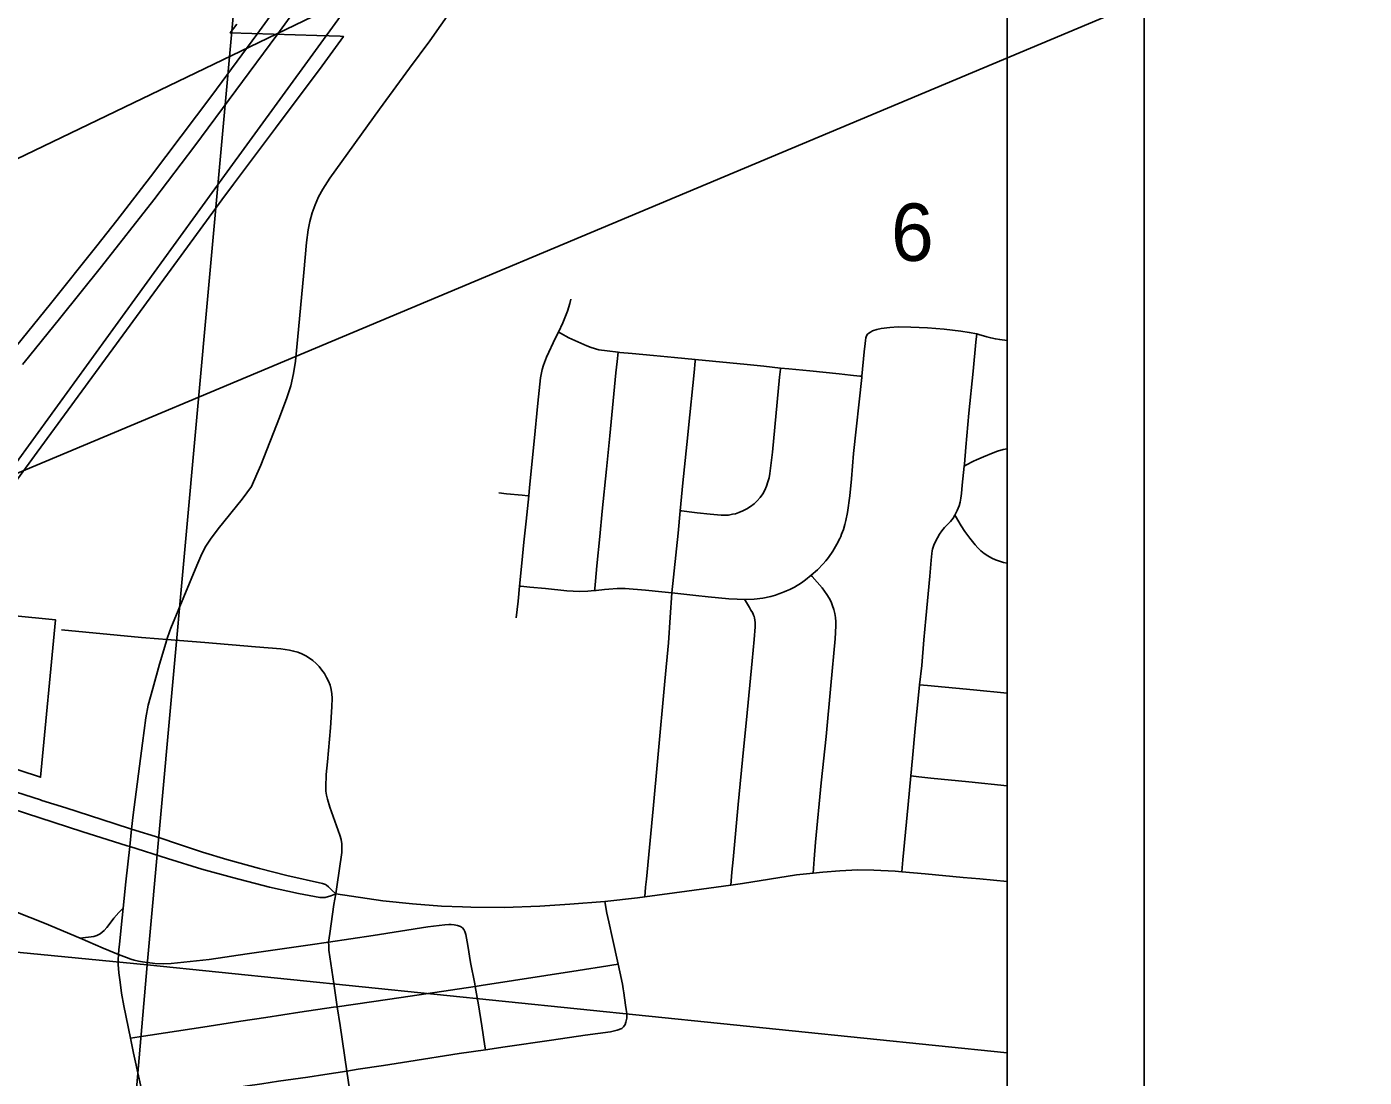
# Model space of a CAD drawing. Extents: x 0 to 34, y 0 to 22.
# Drawn here: x 8.184 to 9.161, y 18.991 to 19.757 of the extents above; entities that cross this region are included whole.
import ezdxf

# ---------------------------------------------------------------- set-up
doc = ezdxf.new("R2010")
doc.units = 0
for name, color, linetype in [('Default', 7, 'Continuous'), ('GM_X_City_Street', 7, 'Continuous'), ('GM_X_County_Road', 7, 'Continuous'), ('GM_X_Rail_Line', 7, 'Continuous'), ('GM_X_Section', 7, 'Continuous'), ('GM_X_Section_Text', 7, 'Continuous'), ('GM_X_State_Route', 7, 'Continuous'), ('GM_X_Township_Road', 7, 'Continuous'), ('GM_X_US_Route', 7, 'Continuous'), ('SC_Shading1', 7, 'Continuous'), ('SH_Data', 7, 'Continuous'), ('SH_Text', 7, 'Continuous')]:
    doc.layers.add(name, color=color, linetype=linetype)

msp = doc.modelspace()

# ---------------------------------------------------------------- linework, layer by layer
at = {"layer": 'Default'}
for points in [[(8.9, 19.00882), (8.9, 20.02755), (8.36301, 20.07599), (8.27199, 19.07297)], [(8.9, 18.00303), (8.9, 19.00882), (8.27199, 19.07297), (8.18593, 18.07293)]]:
    msp.add_lwpolyline(points, close=True, dxfattribs=at)
at = {"layer": 'GM_X_City_Street'}
for points in [[(8.9, 14.09996), (8.9, 20.03076), (8.89121, 20.03126), (8.71075, 20.04151), (8.58587, 20.05322), (8.57205, 20.0545), (8.0393, 20.10354)], [(8.54139, 19.32601), (8.54279, 19.33829), (8.54387, 19.34932), (8.54551, 19.36594), (8.54698, 19.38132), (8.54866, 19.39664), (8.55059, 19.41517), (8.55122, 19.42117), (8.55464, 19.45502), (8.55716, 19.48275), (8.5593, 19.50122), (8.56043, 19.50739), (8.56132, 19.51041), (8.5636, 19.51626), (8.57026, 19.53027), (8.57229, 19.53455), (8.57551, 19.54135), (8.5789, 19.54971), (8.58071, 19.5555), (8.58137, 19.55847)], [(8.79891, 19.53383), (8.8, 19.53453), (8.80162, 19.53538), (8.80463, 19.53638), (8.80798, 19.53717), (8.81415, 19.53802), (8.82035, 19.53832), (8.82965, 19.5382), (8.84178, 19.53777), (8.85398, 19.53672), (8.86615, 19.53534), (8.87222, 19.53436), (8.87762, 19.53323)], [(8.54387, 19.34932), (8.54473, 19.34924), (8.55142, 19.34859), (8.56297, 19.34743), (8.57836, 19.34578), (8.58757, 19.34537), (8.59371, 19.34558), (8.59861, 19.346), (8.59986, 19.34611), (8.606, 19.34674), (8.60905, 19.34704), (8.61509, 19.34744), (8.62099, 19.34756), (8.62695, 19.34711), (8.62991, 19.34682), (8.63578, 19.34623), (8.6479, 19.34507), (8.65505, 19.34426), (8.67255, 19.3425), (8.68151, 19.34137), (8.69668, 19.34007), (8.70281, 19.33961), (8.70815, 19.33953), (8.71512, 19.33962), (8.72143, 19.34041), (8.72725, 19.3416), (8.7308, 19.34268), (8.73317, 19.34357), (8.7358, 19.34455), (8.737, 19.345), (8.73879, 19.34574), (8.74115, 19.34684), (8.74461, 19.34859), (8.74964, 19.35156), (8.7527, 19.35383), (8.75684, 19.35713), (8.76148, 19.36103), (8.76566, 19.36546), (8.76761, 19.36781), (8.76942, 19.37017), (8.77253, 19.37469), (8.77559, 19.37992), (8.77769, 19.38389), (8.77835, 19.38534), (8.77903, 19.38716), (8.78035, 19.3906), (8.78127, 19.39415), (8.78218, 19.39705), (8.78338, 19.403), (8.78499, 19.41518), (8.78615, 19.42756), (8.78782, 19.44591), (8.79368, 19.50153), (8.79378, 19.50236), (8.79549, 19.52013), (8.79618, 19.52623), (8.7964, 19.52851), (8.79675, 19.53027), (8.79729, 19.5319), (8.79798, 19.53298), (8.79891, 19.53383)], [(8.57229, 19.53455), (8.57377, 19.53373), (8.57998, 19.53028), (8.59297, 19.52448), (8.59631, 19.52322), (8.60172, 19.52172), (8.60788, 19.52083), (8.61579, 19.51988), (8.61705, 19.51973), (8.62616, 19.51889), (8.64163, 19.51745), (8.65707, 19.51597), (8.67215, 19.51459), (8.70997, 19.51088), (8.72225, 19.5096), (8.73439, 19.50835), (8.74048, 19.50772), (8.75573, 19.50622), (8.77734, 19.504), (8.78562, 19.50318), (8.79241, 19.5025), (8.79378, 19.50236)], [(8.82292, 19.1408), (8.82376, 19.14968), (8.82754, 19.18986), (8.82957, 19.21075), (8.83083, 19.22385), (8.83274, 19.24542), (8.83599, 19.27719), (8.83747, 19.29139), (8.83915, 19.31003), (8.84053, 19.32552), (8.84349, 19.35639), (8.84437, 19.36813), (8.84487, 19.37316), (8.84518, 19.37493), (8.84546, 19.37612), (8.84567, 19.3769), (8.84643, 19.37905), (8.84761, 19.38184), (8.84897, 19.38455), (8.85051, 19.38715), (8.85227, 19.38959), (8.85423, 19.39194), (8.85844, 19.39646), (8.86043, 19.39891), (8.86177, 19.40112), (8.86344, 19.40442), (8.86479, 19.40788), (8.86554, 19.41042), (8.86605, 19.41337), (8.86643, 19.41684), (8.86707, 19.42287), (8.86856, 19.43677), (8.86873, 19.43829), (8.86978, 19.45068), (8.87197, 19.47537), (8.8751, 19.50615), (8.87704, 19.52719), (8.87762, 19.53323)], [(8.59861, 19.346), (8.59877, 19.34757), (8.59928, 19.3529), (8.60034, 19.36405), (8.60253, 19.38545), (8.60423, 19.40385), (8.6073, 19.43452), (8.60993, 19.45894), (8.61432, 19.50483), (8.61513, 19.5131), (8.61579, 19.51988)], [(8.63531, 19.12253), (8.63596, 19.12972), (8.63649, 19.13553), (8.64139, 19.1868), (8.64493, 19.22401), (8.64995, 19.27986), (8.65255, 19.30777), (8.65398, 19.32636), (8.65505, 19.34426), (8.65973, 19.38786), (8.66123, 19.40419), (8.66171, 19.40937), (8.66319, 19.42466), (8.66595, 19.45267), (8.66812, 19.47408), (8.67048, 19.49568), (8.67132, 19.5051), (8.67213, 19.51327), (8.67215, 19.51459)], [(8.66123, 19.40419), (8.66239, 19.40406), (8.66763, 19.40347), (8.67354, 19.40278), (8.683, 19.40179), (8.6911, 19.401), (8.69326, 19.4009), (8.69504, 19.401), (8.69652, 19.4011), (8.69927, 19.40164), (8.70145, 19.40209), (8.70398, 19.40295), (8.70697, 19.40411), (8.70984, 19.40557), (8.71255, 19.40726), (8.71512, 19.4092), (8.71748, 19.41138), (8.71959, 19.41383), (8.72141, 19.41648), (8.72296, 19.41929), (8.72424, 19.42223), (8.72526, 19.42526), (8.72605, 19.42835), (8.7266, 19.43149), (8.72854, 19.447), (8.73376, 19.50161), (8.7343, 19.50743), (8.73439, 19.50835)], [(8.86856, 19.43677), (8.86975, 19.4374), (8.87526, 19.44032), (8.87759, 19.44144), (8.88264, 19.44357), (8.88965, 19.44658), (8.89286, 19.4477), (8.89695, 19.44887), (8.89995, 19.44949), (8.9, 19.4495)], [(8.52872, 19.41719), (8.53444, 19.41665), (8.54578, 19.41559), (8.54984, 19.41523), (8.55059, 19.41517)], [(8.86177, 19.40112), (8.8622, 19.40037), (8.86624, 19.39325), (8.86902, 19.38908), (8.87252, 19.38424), (8.87644, 19.3794), (8.87852, 19.3771), (8.88069, 19.375), (8.88312, 19.37309), (8.88589, 19.37125), (8.88865, 19.36967), (8.89126, 19.36852), (8.89427, 19.36735), (8.89723, 19.3664), (8.9, 19.36593)], [(8.75824, 19.13979), (8.75904, 19.15002), (8.76001, 19.16246), (8.76414, 19.20572), (8.76765, 19.23964), (8.77108, 19.27684), (8.77433, 19.31091), (8.77481, 19.32018), (8.77479, 19.32325), (8.77459, 19.32626), (8.77413, 19.32921), (8.77343, 19.33211), (8.77249, 19.33497), (8.77131, 19.33775), (8.76992, 19.34045), (8.76835, 19.34308), (8.7648, 19.34805), (8.76125, 19.35216), (8.75758, 19.35629), (8.75684, 19.35713)], [(8.69807, 19.13118), (8.69896, 19.14062), (8.69983, 19.14988), (8.70349, 19.19001), (8.70741, 19.2301), (8.70952, 19.25167), (8.71366, 19.29483), (8.71515, 19.31023), (8.71586, 19.31948), (8.71588, 19.32273), (8.71566, 19.32451), (8.71537, 19.32599), (8.71507, 19.32698), (8.71478, 19.32796), (8.71438, 19.32875), (8.71389, 19.32993), (8.71279, 19.33181), (8.71168, 19.33364), (8.70878, 19.33848), (8.70815, 19.33953)], [(8.40974, 19.12474), (8.41049, 19.12989), (8.41416, 19.15496), (8.41428, 19.15812), (8.41413, 19.16129), (8.41363, 19.16444), (8.41281, 19.16751), (8.40541, 19.18789), (8.40362, 19.19374), (8.40298, 19.19668), (8.4026, 19.19966), (8.40248, 19.20268), (8.4028, 19.21189), (8.40365, 19.2211), (8.40581, 19.24576), (8.40695, 19.26124), (8.40705, 19.2675), (8.40684, 19.27066), (8.40636, 19.2738), (8.40554, 19.27688), (8.40443, 19.27985), (8.40304, 19.2827), (8.40144, 19.28543), (8.39965, 19.28805), (8.39767, 19.29053), (8.39548, 19.29282), (8.3931, 19.29491), (8.39053, 19.29678), (8.3878, 19.29841), (8.38495, 19.2998), (8.382, 19.30096), (8.37898, 19.30184), (8.37591, 19.30252), (8.36971, 19.30338), (8.35119, 19.30504), (8.3142, 19.30823), (8.28653, 19.31033), (8.28026, 19.3108), (8.26795, 19.31187), (8.20947, 19.31744)], [(8.83599, 19.27719), (8.84181, 19.27665), (8.87519, 19.27364), (8.9, 19.27125)], [(8.82957, 19.21075), (8.83536, 19.21019), (8.84413, 19.20924), (8.87193, 19.20636), (8.9, 19.20357)], [(8.4224, 18.96438), (8.41777, 18.99547), (8.41298, 19.02868), (8.41087, 19.04237), (8.40825, 19.05931), (8.4048, 19.08375), (8.40464, 19.08678), (8.40452, 19.08955), (8.40532, 19.09591), (8.40828, 19.11695), (8.40974, 19.12474)], [(8.61866, 19.02659), (8.61975, 19.02767), (8.62103, 19.02945), (8.62162, 19.03103), (8.62231, 19.03409), (8.62216, 19.03736), (8.62182, 19.04038), (8.62133, 19.04366), (8.61993, 19.05262), (8.61945, 19.05549), (8.61895, 19.05881), (8.61714, 19.06793), (8.61593, 19.07336), (8.61175, 19.09227), (8.60909, 19.10432), (8.60775, 19.11062), (8.60613, 19.11909)], [(8.25123, 19.08047), (8.25688, 19.0783), (8.26011, 19.07722), (8.26247, 19.07646), (8.26579, 19.07576), (8.26859, 19.07522), (8.27767, 19.07397), (8.28364, 19.07359), (8.28963, 19.07393), (8.31738, 19.07686), (8.345, 19.08107), (8.39097, 19.08757), (8.40452, 19.08955), (8.43713, 19.09442), (8.47687, 19.10081), (8.48936, 19.10223), (8.49231, 19.10244), (8.49402, 19.10238), (8.49612, 19.10224), (8.49869, 19.10172), (8.50082, 19.10082)], [(8.51902, 19.01105), (8.51863, 19.01361), (8.51634, 19.02845), (8.51387, 19.04376), (8.51153, 19.05726), (8.51118, 19.05922), (8.50819, 19.07461), (8.50604, 19.08704), (8.50458, 19.09499), (8.5039, 19.09728), (8.50322, 19.09876), (8.50217, 19.10001), (8.50082, 19.10082)], [(8.25986, 19.01953), (8.26613, 19.02046), (8.31277, 19.02738), (8.34045, 19.03177), (8.3587, 19.03452), (8.38354, 19.03832), (8.40819, 19.04198), (8.41087, 19.04237), (8.4359, 19.04606), (8.45745, 19.04923), (8.51153, 19.05726), (8.51597, 19.05792), (8.58674, 19.0689), (8.60829, 19.07226), (8.61138, 19.07271), (8.61593, 19.07336)], [(8.26998, 18.97339), (8.27578, 18.97421), (8.30074, 18.97771), (8.33134, 18.98254), (8.34351, 18.98444), (8.3557, 18.98615), (8.36795, 18.988), (8.38941, 18.99113), (8.40168, 18.99294), (8.41777, 18.99547), (8.42619, 18.99679), (8.44459, 18.99961), (8.46298, 19.00248), (8.49977, 19.0082), (8.51902, 19.01105), (8.53343, 19.01317), (8.56731, 19.01791), (8.59187, 19.02162), (8.6103, 19.02408), (8.61511, 19.02521), (8.61866, 19.02659)]]:
    msp.add_lwpolyline(points, dxfattribs=at)
at = {"layer": 'GM_X_County_Road'}
for p, q in [((8.28653, 19.31033), (8.28865, 19.31669)), ((8.25947, 19.15927), (8.26052, 19.17206))]:
    msp.add_line(p, q, dxfattribs=at)
for points in [[(8.28865, 19.31669), (8.28926, 19.31851), (8.30834, 19.36438), (8.31202, 19.37289), (8.31497, 19.37838), (8.31832, 19.38361), (8.32382, 19.3911), (8.34133, 19.41258), (8.34819, 19.42192), (8.35214, 19.4308), (8.35493, 19.43754), (8.3686, 19.47222), (8.37406, 19.48664), (8.37682, 19.49539), (8.37891, 19.50429), (8.38035, 19.51336), (8.38337, 19.54416), (8.38635, 19.57813), (8.3884, 19.5998), (8.3896, 19.60913), (8.39086, 19.61534), (8.39258, 19.62144), (8.39466, 19.62741), (8.39722, 19.63323), (8.40023, 19.63881), (8.40535, 19.64676), (8.44163, 19.69711), (8.46362, 19.72716), (8.47831, 19.74712), (8.49454, 19.76985)], [(8.26052, 19.17206), (8.2618, 19.18247), (8.26856, 19.23456), (8.27109, 19.25324), (8.27281, 19.26237), (8.27627, 19.27462), (8.28112, 19.29229), (8.28571, 19.30771), (8.28653, 19.31033)], [(8.25458, 19.11429), (8.25656, 19.13357), (8.25947, 19.15927)], [(8.22325, 19.09242), (8.23309, 19.09371), (8.2353, 19.09441), (8.23773, 19.09557), (8.24075, 19.09813), (8.24273, 19.10022), (8.24516, 19.10347), (8.24783, 19.10707), (8.25143, 19.11125), (8.25458, 19.11429)], [(8.25123, 19.08047), (8.25146, 19.08425), (8.25175, 19.08781), (8.25313, 19.10016), (8.25458, 19.11429)], [(8.25986, 19.01953), (8.25492, 19.04315), (8.25327, 19.05236), (8.25229, 19.06041), (8.25146, 19.06715), (8.25101, 19.07333), (8.25094, 19.07651), (8.25123, 19.08047)], [(8.26998, 18.97339), (8.26215, 19.00862), (8.25986, 19.01953)]]:
    msp.add_lwpolyline(points, dxfattribs=at)
at = {"layer": 'GM_X_Rail_Line'}
msp.add_lwpolyline([(7.67235, 18.74566), (7.7577, 18.86316), (7.81105, 18.93663), (7.81658, 18.9442), (7.90608, 19.06726), (8.04779, 19.26227), (8.10524, 19.34153), (8.12591, 19.36986), (8.13806, 19.38663), (8.14993, 19.40304), (8.32663, 19.64609), (8.45952, 19.82871), (8.76287, 20.24597), (8.77342, 20.26036), (8.81967, 20.3248), (8.84497, 20.35923), (8.9, 20.435)], dxfattribs=at)
at = {"layer": 'GM_X_Section'}
for points in [[(8.36301, 20.07599), (8.27199, 19.07297), (7.26758, 19.17046), (7.35437, 20.16973)], [(7.26758, 19.17046), (8.27199, 19.07297), (8.18593, 18.07293), (7.17505, 18.16824)]]:
    msp.add_lwpolyline(points, close=True, dxfattribs=at)
at = {"layer": 'GM_X_State_Route'}
for points in [[(8.25757, 19.15986), (8.2244, 19.17025), (8.16292, 19.19008), (8.03475, 19.23145), (8.00536, 19.24105), (8.00232, 19.24205)], [(8.19523, 19.19297), (8.19431, 19.19326), (8.14741, 19.20814)], [(8.26052, 19.17206), (8.24796, 19.17597), (8.2127, 19.1874), (8.19523, 19.19297)], [(8.40974, 19.12474), (8.40692, 19.12749), (8.40442, 19.12993), (8.40307, 19.13098), (8.40216, 19.13152), (8.40015, 19.13234), (8.37405, 19.13817), (8.35417, 19.14324), (8.3303, 19.14972), (8.31251, 19.15505), (8.29493, 19.16092), (8.28134, 19.16554), (8.26052, 19.17206)], [(8.40974, 19.12474), (8.40613, 19.12336), (8.40195, 19.12213), (8.39818, 19.12215), (8.38261, 19.12495), (8.36141, 19.12954), (8.33425, 19.13666), (8.31208, 19.14287), (8.28688, 19.15043), (8.25947, 19.15927), (8.25757, 19.15986)], [(8.9, 19.13378), (8.87987, 19.13559), (8.86783, 19.13668), (8.83992, 19.13933), (8.82292, 19.1408), (8.81812, 19.14121), (8.80263, 19.1421), (8.79079, 19.1422), (8.77777, 19.1416), (8.76534, 19.14052), (8.75824, 19.13979), (8.7462, 19.13855), (8.70655, 19.13233), (8.69807, 19.13118), (8.66611, 19.12681), (8.63531, 19.12253), (8.62991, 19.12178), (8.60613, 19.11909)], [(8.50217, 19.11526), (8.48698, 19.11586), (8.46567, 19.11754), (8.44416, 19.11971), (8.40974, 19.12474)], [(8.60613, 19.11909), (8.58058, 19.11714), (8.55869, 19.11582), (8.53275, 19.11482), (8.50824, 19.11503), (8.50217, 19.11526)]]:
    msp.add_lwpolyline(points, dxfattribs=at)
at = {"layer": 'GM_X_Township_Road'}
for points in [[(8.87762, 19.53323), (8.87917, 19.53274), (8.88493, 19.53102), (8.88791, 19.53033), (8.89125, 19.52964), (8.89448, 19.52906), (8.9, 19.5285)], [(7.9978, 19.17437), (8.02481, 19.16564), (8.0484, 19.15747), (8.07512, 19.14887), (8.10504, 19.13907), (8.12273, 19.13262), (8.14647, 19.12381), (8.17244, 19.11329), (8.17626, 19.11171), (8.19711, 19.1033), (8.22325, 19.09242)], [(8.22325, 19.09242), (8.23985, 19.08508), (8.25123, 19.08047)]]:
    msp.add_lwpolyline(points, dxfattribs=at)
at = {"layer": 'GM_X_US_Route'}
for points in [[(8.36665, 19.75122), (8.49564, 19.92868), (8.51952, 19.96087), (8.56692, 20.02632), (8.5861, 20.05269), (8.61874, 20.0976), (8.7109, 20.22371), (8.7419, 20.26626)], [(8.14754, 19.48879), (8.20146, 19.55514), (8.23537, 19.59755), (8.24995, 19.61607), (8.27456, 19.64785), (8.31938, 19.70707), (8.35208, 19.75161), (8.4308, 19.85986)], [(8.18111, 19.51086), (8.18237, 19.51241), (8.20804, 19.54414), (8.23863, 19.58235), (8.27701, 19.63099), (8.30691, 19.67044), (8.36665, 19.75122)]]:
    msp.add_lwpolyline(points, dxfattribs=at)
at = {"layer": 'SC_Shading1'}
for points in [[(8.9, 15.77244), (8.9, 20.52647)], [(8.33756, 19.75917), (8.3327, 19.75276), (8.39585, 19.75086), (8.40489, 19.75059), (8.41302, 19.75034), (8.41527, 19.75028), (8.39977, 19.72883), (8.36577, 19.6834), (8.33509, 19.6424), (8.3265, 19.63093), (8.29692, 19.5905), (8.19183, 19.44689), (8.10931, 19.33413), (8.20509, 19.32476), (8.19422, 19.20985), (8.05234, 19.25627)]]:
    msp.add_lwpolyline(points, dxfattribs=at)
at = {"layer": 'SH_Data'}
for p, q in [((9, 20.99996), (9, 13.99996)), ((8.9, 20.89996), (8.9, 14.09996))]:
    msp.add_line(p, q, dxfattribs=at)
at = {"layer": 'SH_Text'}
msp.add_lwpolyline([(9.24529, 20.17502), (4.46592, 17.8756), (9.24529, 19.87959)], close=True, dxfattribs=at)

# ---------------------------------------------------------------- texts
at = {"layer": 'GM_X_Section_Text'}
msp.add_text('6', height=0.04186, rotation=0.00001, dxfattribs=at).set_placement((8.81511, 19.58651))

doc.saveas('drawing.dxf')
